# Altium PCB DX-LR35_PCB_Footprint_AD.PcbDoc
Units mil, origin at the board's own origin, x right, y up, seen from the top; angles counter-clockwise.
Board outline 6000 x 4000 mil, 2 copper layers (Top Layer, Bottom Layer); 1 components, 0 nets, 22 pads, 0 vias.
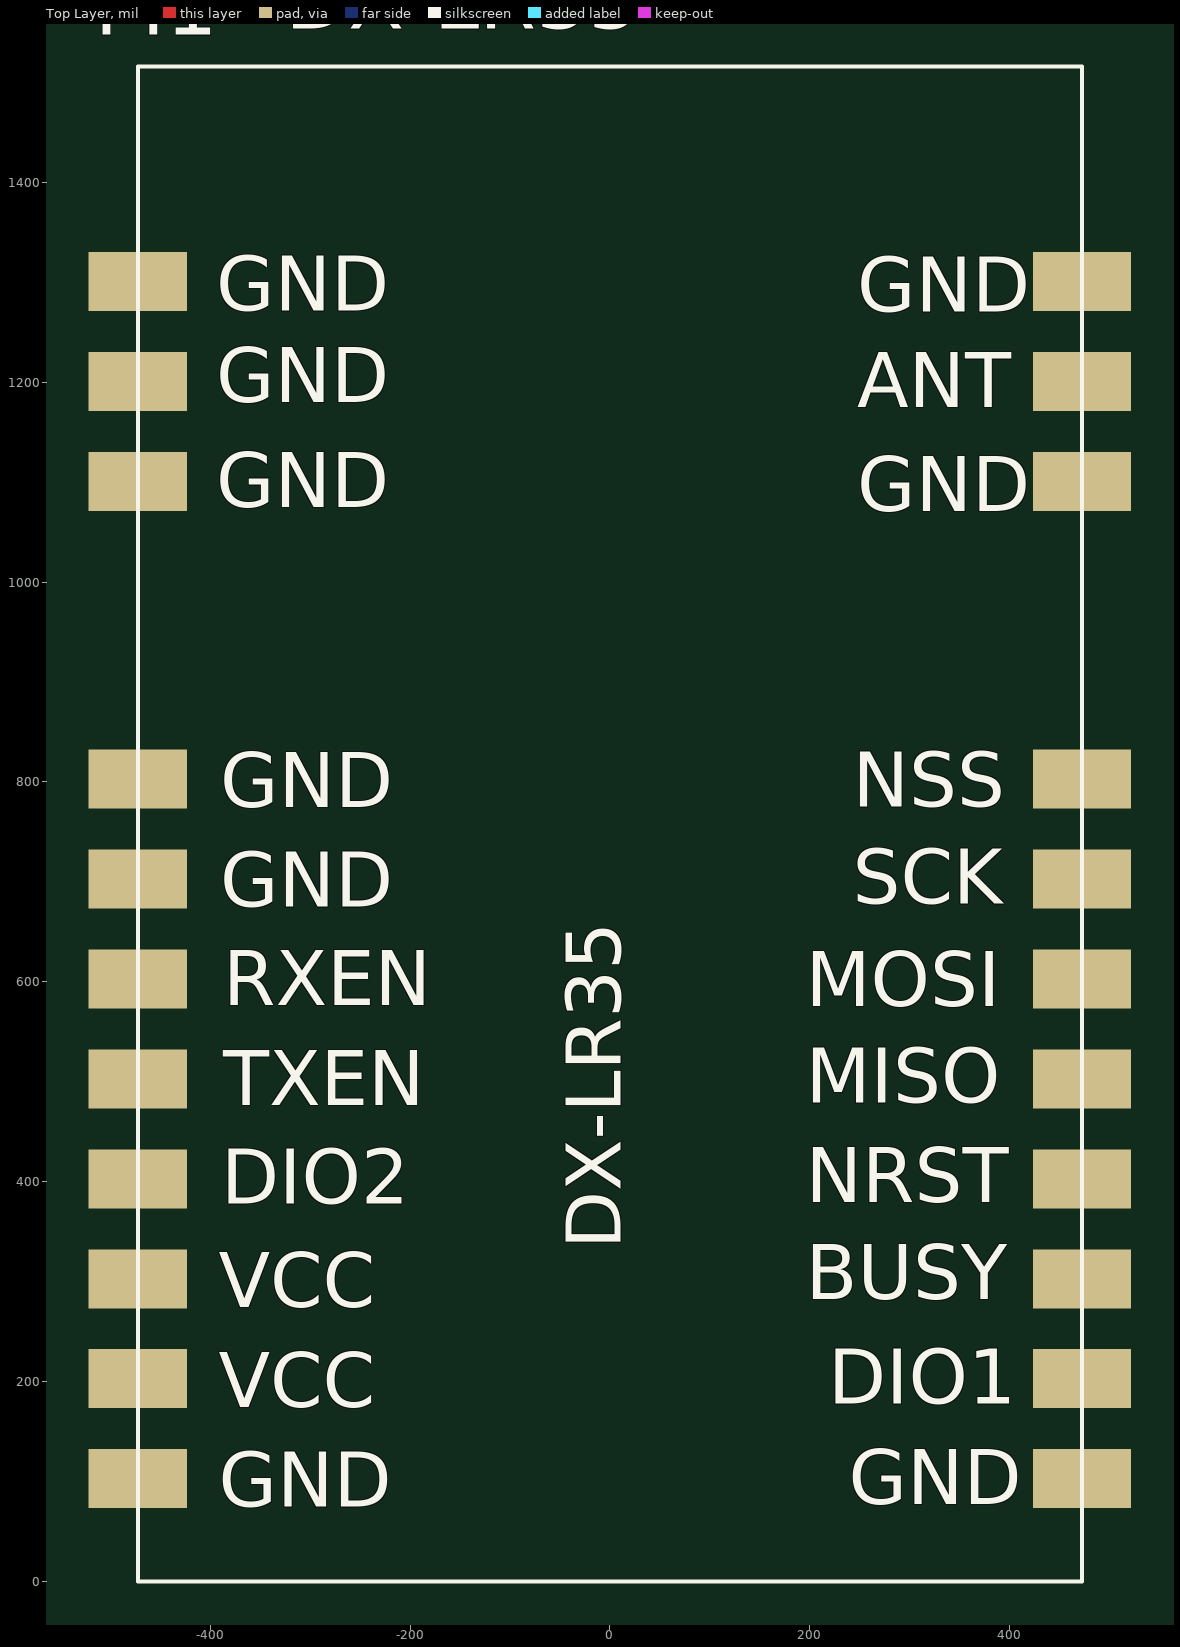
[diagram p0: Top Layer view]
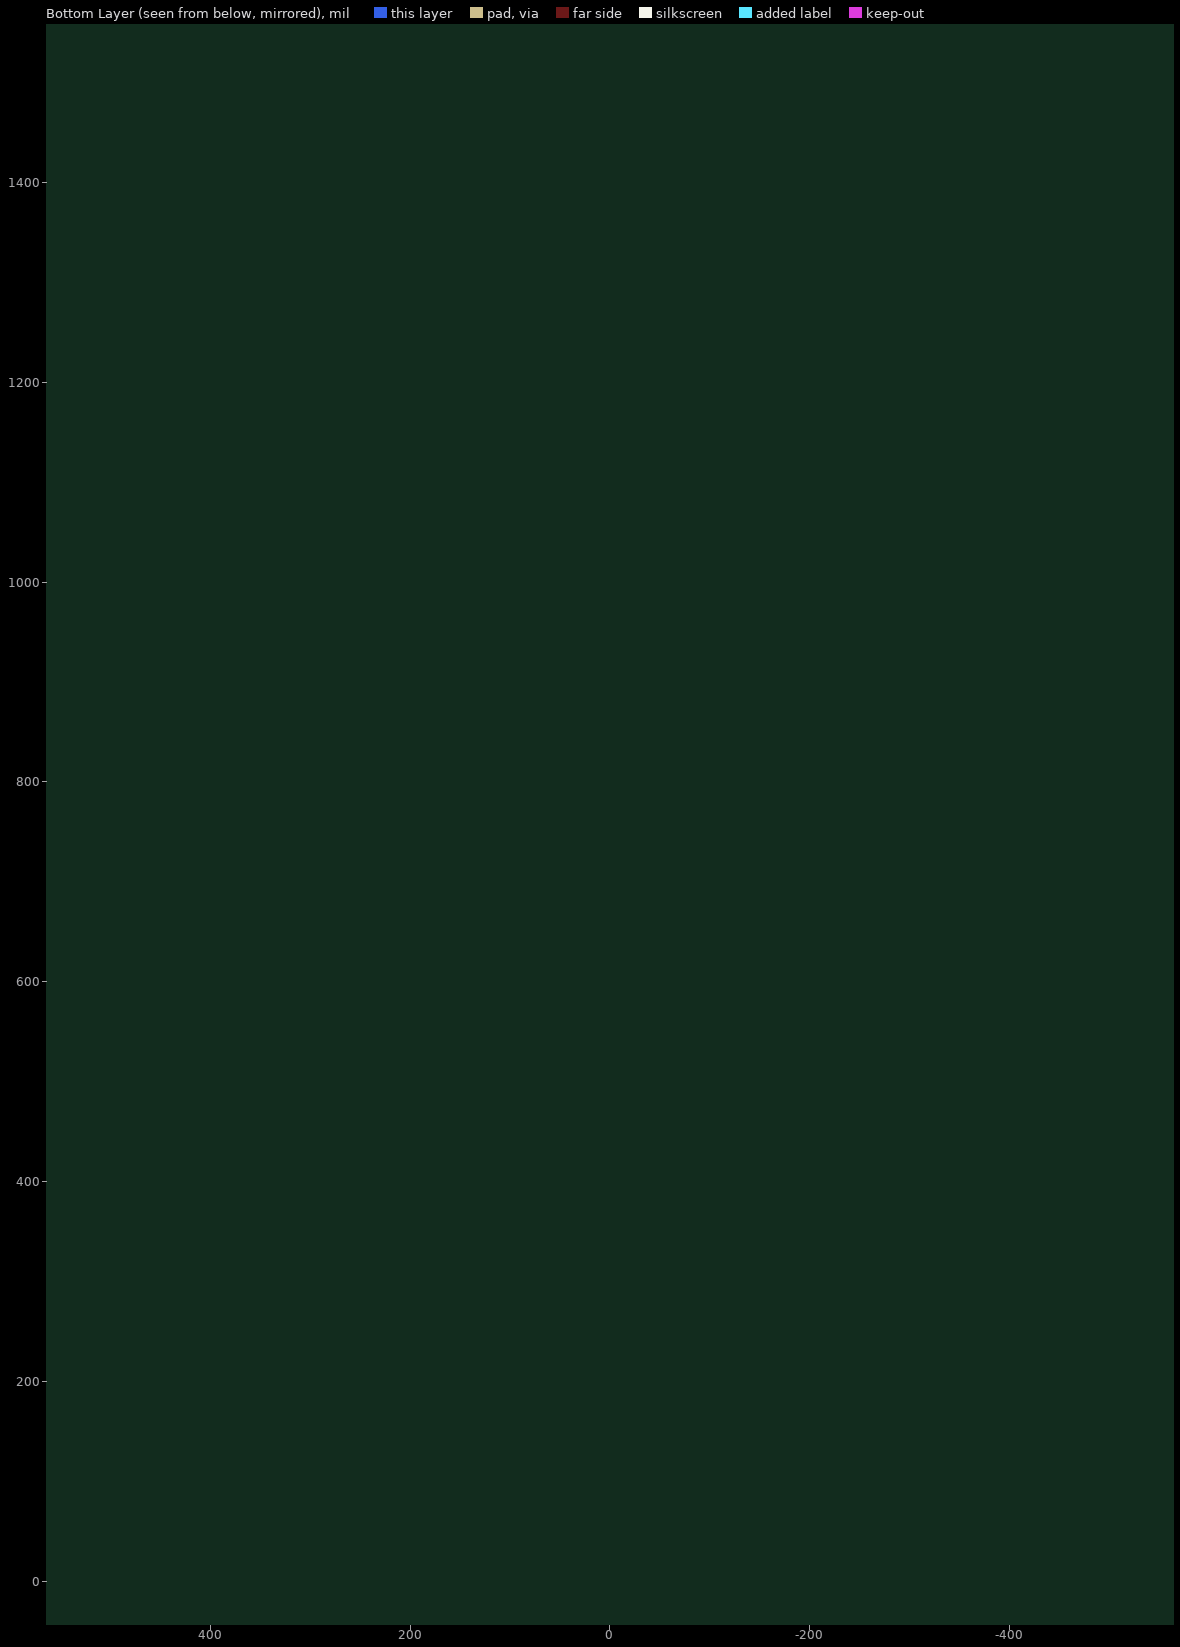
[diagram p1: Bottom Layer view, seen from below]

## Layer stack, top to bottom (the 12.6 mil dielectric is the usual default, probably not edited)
Top Solder: solder mask 0.4, Solder Resist, Dk 3.5
Top Layer: signal copper 1.4
Dielectric 1: dielectric 12.6, FR-4, Dk 4.8
Bottom Layer: signal copper 1.4
Bottom Solder: solder mask 0.4, Solder Resist, Dk 3.5

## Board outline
-3110.15,-791.16 2889.85,-791.16 2889.85,3208.84 -3110.15,3208.84

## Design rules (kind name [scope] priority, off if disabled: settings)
Clearance [All] p1: gap=10 ignorepadtopadclearanceinfootprint=FALSE except(0: Arc-Hole Track-Hole SMDPad-Hole THPad-Hole Via-Hole Fill-Hole Poly-Hole Region-Hole Text-Hole)
PolygonConnect [All] p1: connectstyle=Relief reliefconductorwidth=10 reliefentries=4 polygonreliefangle="90 Angle" airgapwidth=10
RoutingVias [All] p1: holewidth=28 width=50 viastyle="Through Hole" minholewidth=28 minwidth=50 maxholewidth=28 maxwidth=50
SolderMaskExpansion [All] p1: expansion=4 istentingtop=FALSE
Width [All] p1: maxlimit=10 minlimit=10 preferedwidth=10
30 further rules are at their usual default settings.

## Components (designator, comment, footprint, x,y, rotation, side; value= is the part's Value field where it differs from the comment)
M1 "DX-LR35" DX-LR35 -472.44,1300.79 r90 top

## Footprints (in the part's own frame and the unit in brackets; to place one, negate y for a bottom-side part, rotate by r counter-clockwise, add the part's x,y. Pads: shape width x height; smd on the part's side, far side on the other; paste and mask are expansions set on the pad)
DX-LR35 [mm] "38.5mm*24mm*3.8mm-S"
  rect 1.5x2.5 smd: 1(0,0) 2(-2.54,0) 3(-5.08,0) 4(-12.65,0) 5(-15.19,0) 6(-17.73,0) 7(-20.27,0) 8(-22.81,0) 9(-25.35,0) 10(-27.89,0) 11(-30.43,0) 12(-30.43,-24) 13(-27.89,-24) 14(-25.35,-24) 15(-22.81,-24) 16(-20.27,-24) 17(-17.73,-24) 18(-15.19,-24) 19(-12.65,-24) 20(-5.08,-24) 21(-2.54,-24) 22(0,-24)
  silkscreen extent -33.04,-24 5.46,0

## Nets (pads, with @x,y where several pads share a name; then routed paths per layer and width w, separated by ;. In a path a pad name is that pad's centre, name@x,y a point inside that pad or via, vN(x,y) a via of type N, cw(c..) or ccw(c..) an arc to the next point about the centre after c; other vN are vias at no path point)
pads on no net: M1.1 M1.2 M1.3 M1.4 M1.5 M1.6 M1.7 M1.8 M1.9 M1.10 M1.11 M1.12 M1.13 M1.14 M1.15 M1.16 M1.17 M1.18 M1.19 M1.20 M1.21 M1.22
